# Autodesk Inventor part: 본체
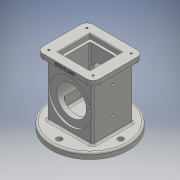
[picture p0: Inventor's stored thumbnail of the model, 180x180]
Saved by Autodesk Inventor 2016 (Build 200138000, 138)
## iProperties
Created: 2018-10
Part Number: 본체
Material: 일반
Document SubType Name: Modeling
Designer: USER
Density: 1 g/cm^3
Appearance: 기본값
Author: USER
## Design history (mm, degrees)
sketch "스케치3"
  geometry: C1 r 62.5 at (0, 0); 1 further point
  constraints: 1 centre point, 1 coincident
  dimensions: "d4" = 125 diameter of C1
extrude "돌출2" new body sketch "스케치3" distance "d5" = 10; taper "d6" = 0 deg
sketch "스케치4"
  geometry: L1 (-37, -33)-(37, -33); L2 (37, -33)-(37, 33); L3 (37, 33)-(-37, 33); L4 (-37, 33)-(-37, -33); L5 (-37, -33)-(37, 33); L6 (37, -33)-(-37, 33); 1 further point
  constraints: 12 end point, 2 midpoint, 2 parallel, 1 horizontal, 1 perpendicular
  dimensions: "d7" = 74 distance of L2.end L3.end; "d8" = 66 distance of L1.end L2.end
extrude "돌출3" join sketch "스케치4" distance "d9" = 88; taper "d10" = 0 deg
sketch "스케치5"
  geometry: L1 (-46, -41)-(46, -41); L2 (46, -41)-(46, 41); L3 (46, 41)-(-46, 41); L4 (-46, 41)-(-46, -41); L5 (-46, -41)-(46, 41); L6 (46, -41)-(-46, 41); 1 further point
  constraints: 12 end point, 2 midpoint, 2 parallel, 1 horizontal, 1 perpendicular
  dimensions: "d11" = 92 distance of L2.end L3.end; "d12" = 82 distance of L1.end L2.end
extrude "돌출4" join sketch "스케치5" distance "d13" = 10; taper "d14" = 0 deg
sketch "스케치6"
  geometry: L1 (-26, -26)-(26, -26); L2 (26, -26)-(26, 26); L3 (26, 26)-(-26, 26); L4 (-26, 26)-(-26, -26); L5 (-26, -26)-(26, 26); L6 (26, -26)-(-26, 26); 1 further point
  constraints: 12 end point, 2 midpoint, 2 parallel, 1 horizontal, 1 perpendicular
  dimensions: "d15" = 52 distance of L2.end L3.end; "d16" = 52 distance of L1.end L2.end
extrude "돌출5" cut sketch "스케치6" distance "d17" = 8; taper "d18" = 0 deg
sketch "스케치7"
  geometry: L1 (-22, -22)-(22, -22); L2 (22, -22)-(22, 22); L3 (22, 22)-(-22, 22); L4 (-22, 22)-(-22, -22); L5 (-22, -22)-(22, 22); L6 (22, -22)-(-22, 22); 1 further point
  constraints: 12 end point, 2 midpoint, 2 parallel, 1 horizontal, 1 perpendicular
  dimensions: "d19" = 44 distance of L2.end L3.end; "d20" = 44 distance of L1.end L2.end
extrude "돌출6" cut sketch "스케치7" distance "d21" = 74; taper "d22" = 0 deg
sketch "스케치8"
  geometry: C1 r 28 at (0, 0); 1 further point
  constraints: 1 centre point, 1 coincident
  dimensions: "d23" = 56 diameter of C1
extrude "돌출7" cut sketch "스케치8" distance "d24" = 18; taper "d25" = -10 deg
sketch "스케치9"
  geometry: L1 (74, 0)-(0, 0) reference; L2 (74, 0)-(74, 88) reference; L3 (0, 88)-(74, 88) reference; L4 (0, 0)-(0, 88) reference; L5 (99.5, 0)-(-25.5, 0) reference; L6 (-25.5, -10)-(99.5, -10) reference; 2 further points
  dimensions: "d26" = 54 distance from line of L6 point (37, 44); "d27" = 37 distance from line of L2 point (37, 44)
hole "구멍1" sketch "스케치9" at (37, 44) diameter "d28" = 48; stored, may be unused: countersink angle "d32" = 90 deg, drill point angle "d34" = 0 deg; dims "d29" = 6, "d30" = 70, "d31" = 3, "d33" = 11
sketch "스케치10"
  geometry: C1 r 24 at (37, -44) reference; C2 r 35 at (37, -44); 1 further point
  constraints: 1 centre point, 1 coincident
  dimensions: "d35" = 70 diameter of C2
extrude "돌출8" cut sketch "스케치10" distance "d36" = 3; taper "d37" = 0 deg
fillet "모깎기1" dims "d38" = 3
sketch "스케치11"
  geometry: 2 further points
  constraints: 1 vertical alignment
  dimensions: "d39" = 50 distance of point (0, 0) point (0, 50)
hole "구멍2" sketch "스케치11" at (0, 50) diameter "d40" = 9; stored, may be unused: countersink angle "d44" = 90 deg, drill point angle "d46" = 118 deg; dims "d41" = 6, "d42" = 70, "d43" = 3, "d45" = 11
sketch "스케치12"
  geometry: L1 (10, -29.5)-(10, 95.5) reference; L2 (0, 66)-(-88, 66) reference; 3 further points
  constraints: 1 horizontal alignment
  dimensions: "d50" = 37 distance from line of L1 point (-27, 33); "d51" = 43 distance of point (-27, 33) point (-70, 33); "d52" = 33 distance from line of L2 point (-27, 33)
hole "구멍3" sketch "스케치12" at (-27, 33), (-70, 33) diameter "d53" = 4.134; stored, may be unused: countersink angle "d57" = 90 deg, drill point angle "d59" = 118 deg; dims "d54" = 30, "d55" = 70, "d56" = 3, "d58" = 30
sketch "스케치13"
  geometry: L1 (46, 41)-(-46, 41) reference; L2 (46, -41)-(46, 41) reference; 2 further points
  dimensions: "d60" = 10 distance from line of L1 point (36, 31); "d61" = 10 distance from line of point (36, 31) L2
hole "구멍4" sketch "스케치13" at (36, 31) diameter "d62" = 3.242; stored, may be unused: countersink angle "d66" = 90 deg, drill point angle "d68" = 118 deg; dims "d63" = 4, "d64" = 70, "d65" = 3, "d67" = 6
sketch "스케치14"
  geometry: C1 r 24 at (0, 0) reference; 2 further points
  constraints: 1 vertical alignment
  dimensions: "d75" = 29 distance of C1.centre point (0, 29)
hole "구멍5" sketch "스케치14" at (0, 29) diameter "d76" = 3.242; stored, may be unused: countersink angle "d80" = 90 deg, drill point angle "d82" = 118 deg; dims "d77" = 4, "d78" = 70, "d79" = 3, "d81" = 6
node "작업 평면1"
fillet "모깎기2" dims "d87" = 3
chamfer "모따기1" distance "d88" = 1; stored, may be unused: second distance "d89" = 2, angle "d90" = 45 deg
fillet "모깎기4" dims "d92" = 3
fillet "모깎기5" dims "d93" = 3
fillet "모깎기6" dims "d94" = 3
fillet "모깎기7" dims "d95" = 3
fillet "모깎기8" dims "d96" = 10
fillet "모깎기9" dims "d97" = 3
fillet "모깎기10" dims "d98" = 3
sketch "스케치15"
  geometry: L1 (0, 0)-(72, 0) reference; L2 (-10, 0)-(-10, -7) reference; 2 further points
  constraints: 1 other
  dimensions: "d99" = 4 distance from line of L1 point (36, -4); "d100" = 46 distance from line of point (36, -4) L2
feature "엠보싱1" sketch "스케치15" dims "d13" = 10, "d101" = 0.5, "d102" = 0
node "솔리드2"
pattern_circular "원형 패턴1" dims angle "d48" = 360 deg
pattern_linear "직사각형 패턴1" dims "d71" = 72, "d74" = 62
pattern_circular "원형 패턴2" dims angle "d84" = 360 deg
mirror "대칭1"
node "투영된 루프1"
other parameters: "d86" = 0
